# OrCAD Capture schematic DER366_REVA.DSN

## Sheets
1 PAGE2: size A
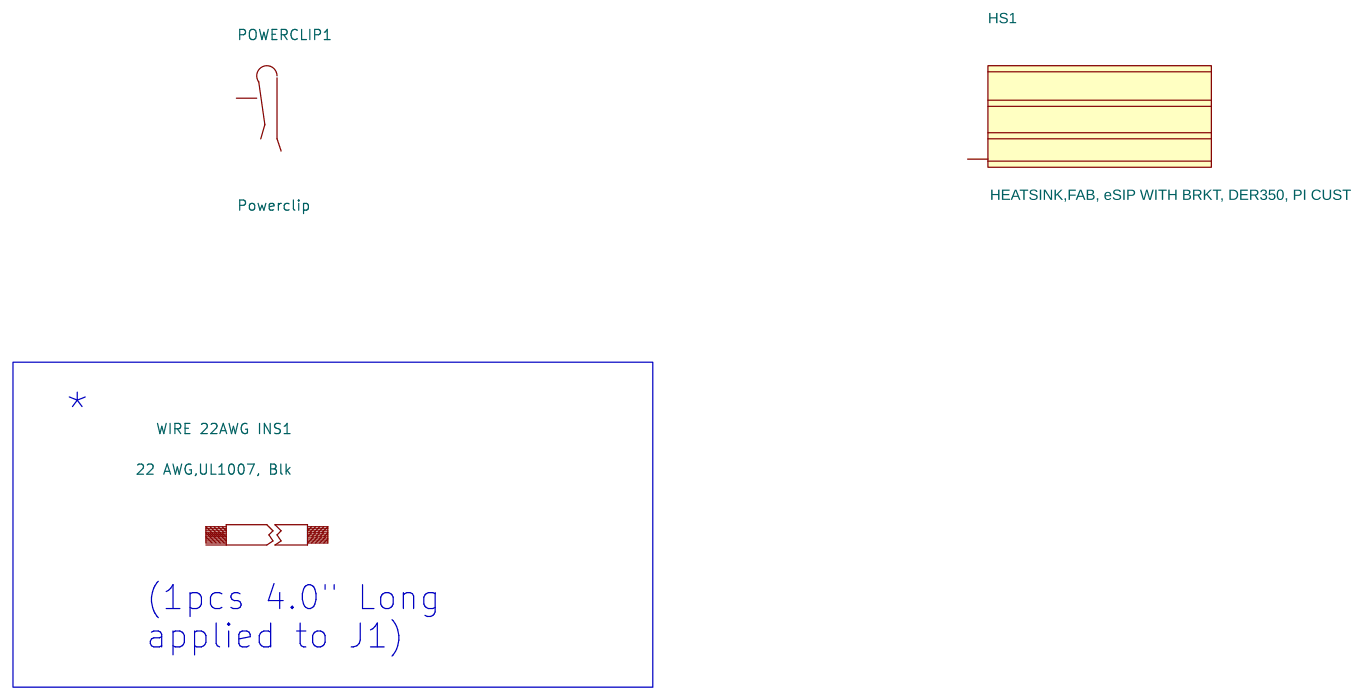
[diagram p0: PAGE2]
2 PAGE1: size C
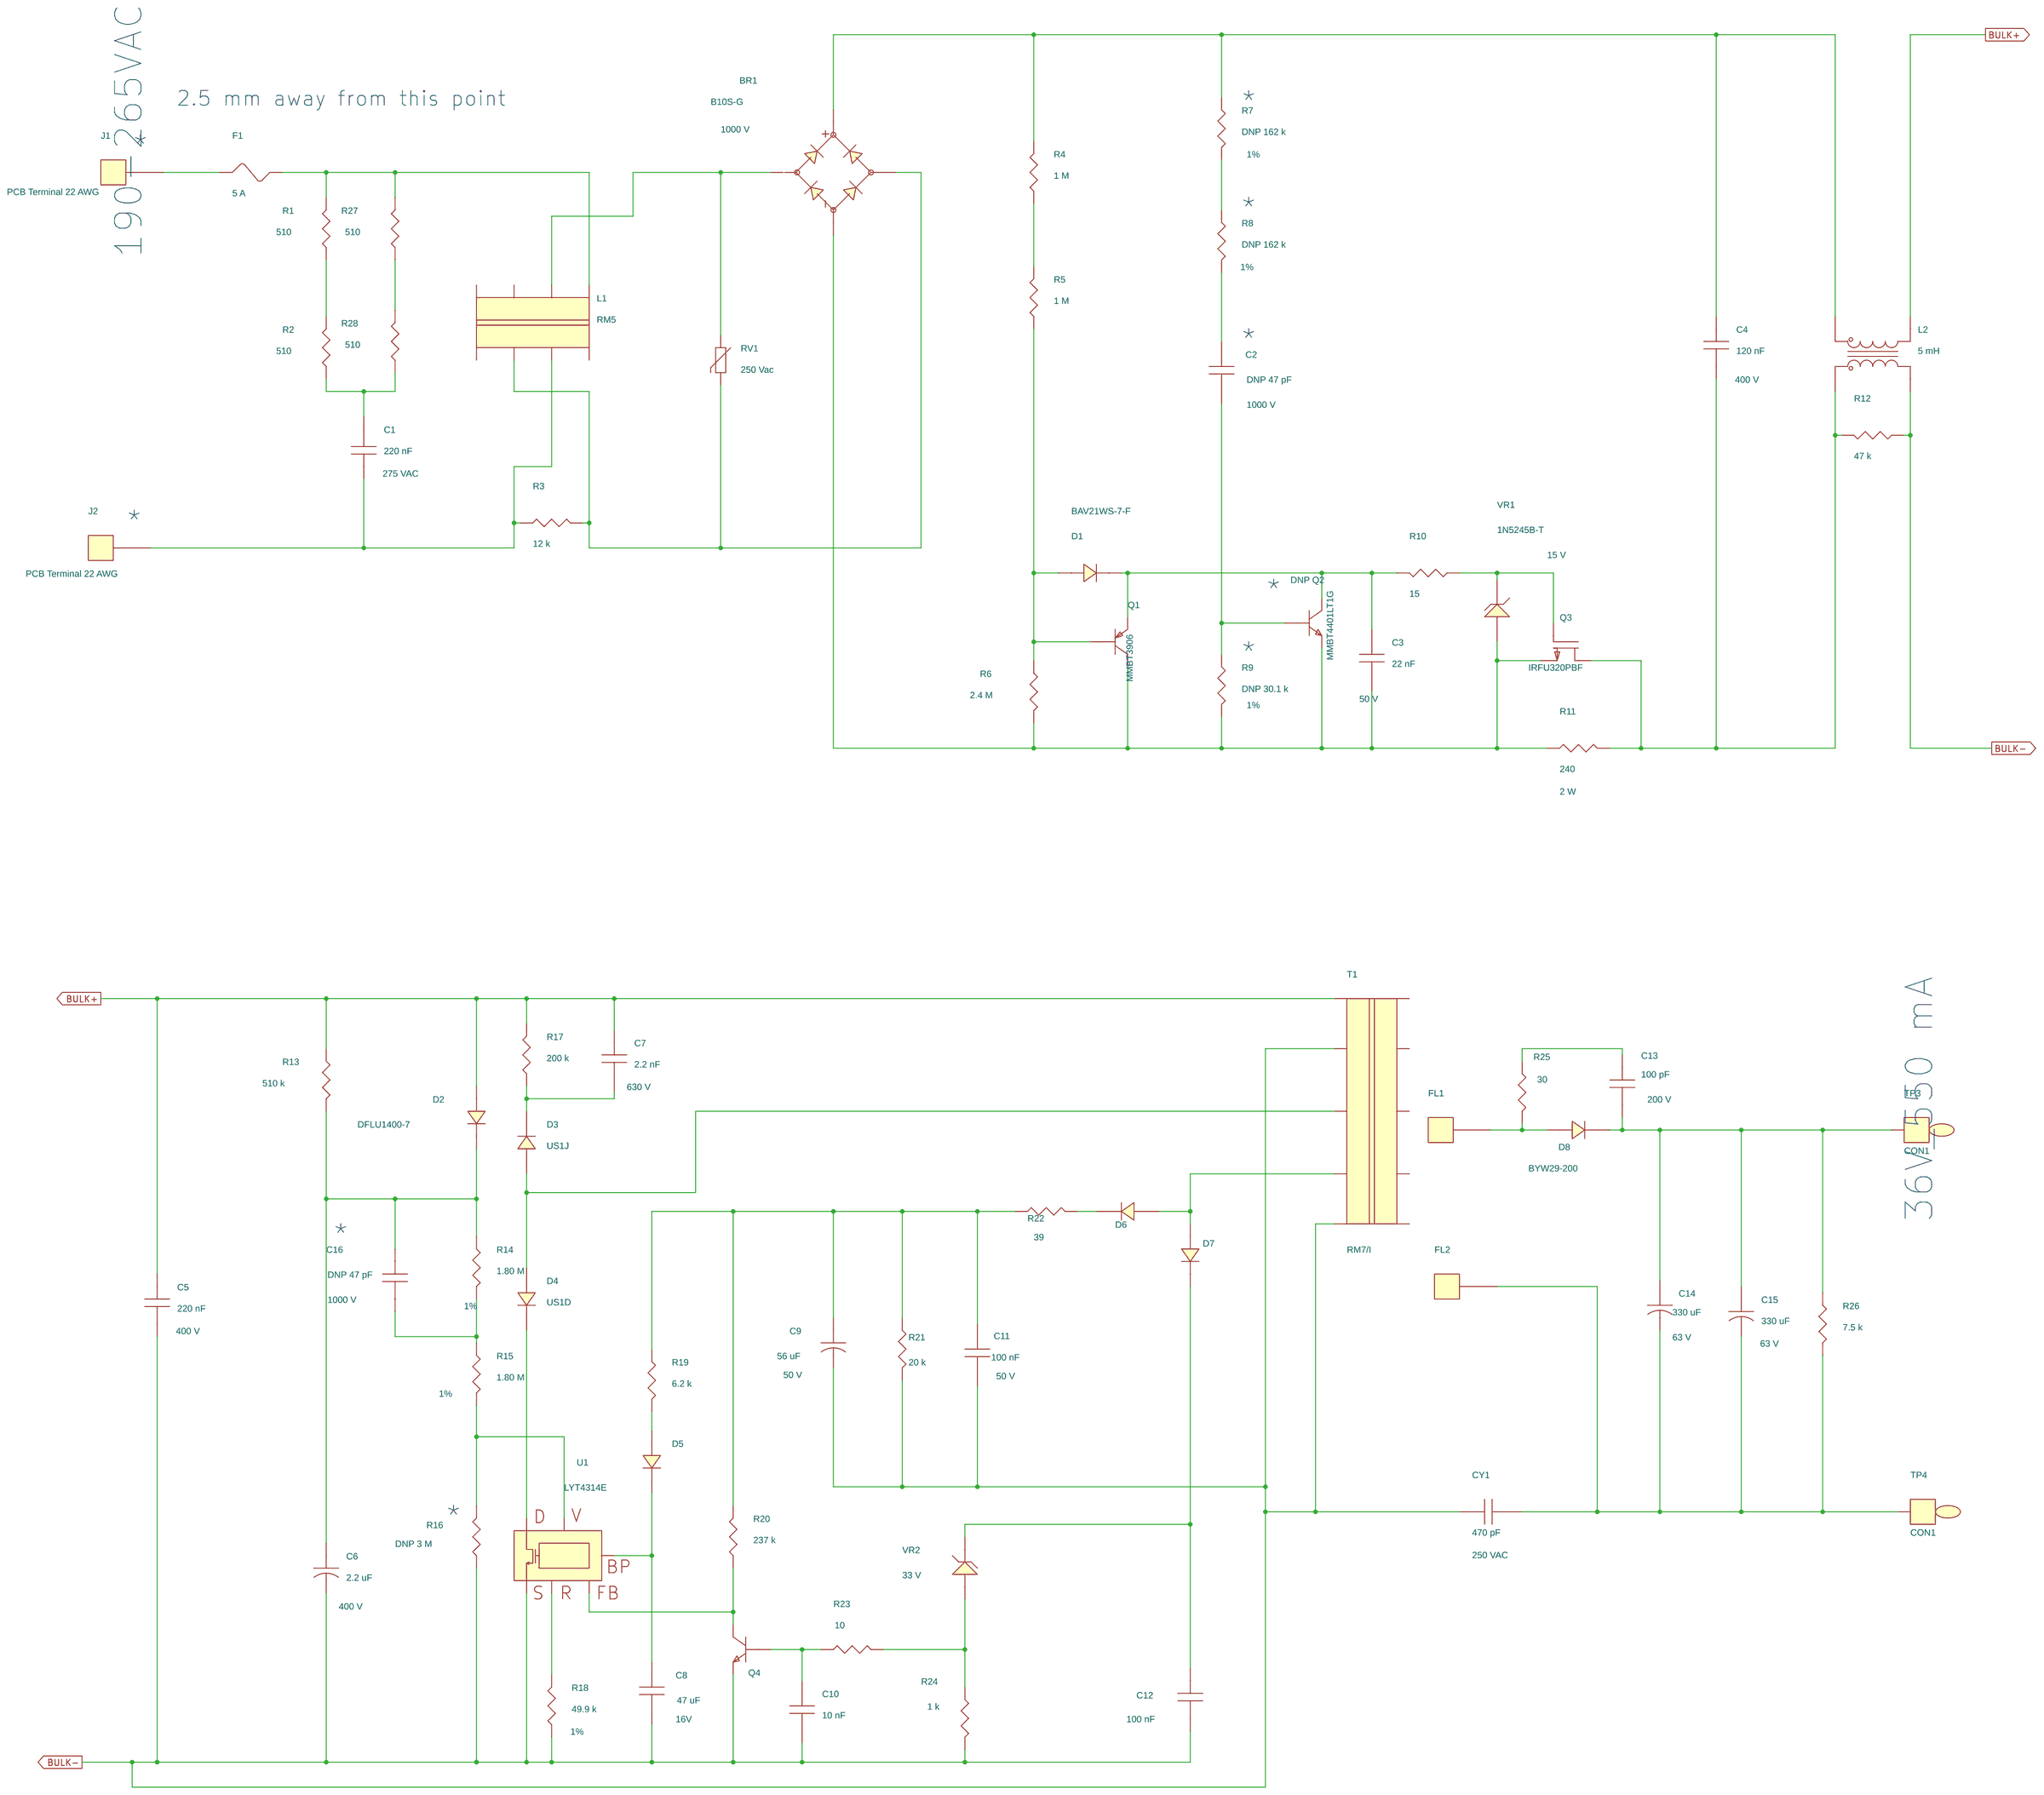
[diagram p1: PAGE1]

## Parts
sheet PAGE1
BR1  B10S-G  [pismsoic4]
C1  220 nF  [pi_np_xcap_rad550x330ls493d040]
C2  DNP 47 pF  [pismc0805]
C3  22 nF  [pismc0603]
C4  120 nF  [pinpcr730x200ls590d40]
C5  220 nF  [pinpcaprad730x230590050]
C6  2.2 uF  [pipolcapcyld250ls100030]
C7  2.2 nF  [pismc1206]
C8  47 uF  [pismc1206]
C9  56 uF  [pipolcapcyld250ls100030]
C10  10 nF  [pismc0603]
C11  100 nF  [pismc0805]
C12  100 nF  [pismc0603]
C13  100 pF  [pismc0805]
C14  330 uF  [pipolcapcyld400ls200040]
C15  330 uF  [pipolcapcyld400ls200040]
C16  DNP 47 pF  [pismc0805]
CY1  470 pF  [pinpcaprad394x275394030]
D1  BAV21WS-7-F  [pismsod323]
D2  DFLU1400-7  [pismddflr120012]
D3  US1J  [pismdsma]
D4  US1D  [pismdsma]
D5  BAV16WS-7-F  [pismsod323]
D6  BAV21WS-7-F  [pismsod323]
D7  BAV21WS-7-F  [pismsod323]
D8  BYW29-200  [pidvt0220acreva]
DNP Q2  MMBT4401LT1G  [pismsot23132]
F1  5 A  [pi_v_axial_160ls150d030]
FL1  PCB Terminal 22 AWG  [pi_hole_22awg]
FL2  PCB Terminal 22 AWG  [pi_hole_22awg]
J1  PCB Terminal 22 AWG  [pi_hole_22awg]
J2  PCB Terminal 22 AWG  [pi_hole_22awg]
L1  RM5  [pi_bobbin_rm5_6p_clp]
L2  5 mH  [piind4p615x420ls350x270040]
Q1  MMBT3906  [pismsot23132]
Q3  IRFU320PBF  [pi_to251aa_123]
Q4  MMBT3904  [pismsot23132]
R1  510  [pismr2512]
R2  510  [pismr2512]
R3  12 k  [pismr0805]
R4  1 M  [pismr1206]
R5  1 M  [pismr1206]
R6  2.4 M  [pismr0805]
R7  DNP 162 k  [pismr1206]
R8  DNP 162 k  [pismr1206]
R9  DNP 30.1 k  [pismr0603]
R10  15  [pismr0603]
R11  240  [pi2wresd200ls725d040]
R12  47 k  [pismr1206]
R13  510 k  [pismr0805]
R14  1.80 M  [pismr1206]
R15  1.80 M  [pismr1206]
R16  DNP 3 M  [pismr0603]
R17  200 k  [pismr1206]
R18  49.9 k  [pismr0603]
R19  6.2 k  [pismr1206]
R20  237 k  [pismr0805]
R21  20 k  [pismr0805]
R22  39  [pismr0805]
R23  10  [pismr0603]
R24  1 k  [pismr0603]
R25  30  [pismr1206]
R26  7.5 k  [pismr1206]
R27  510  [pismr2512]
R28  510  [pismr2512]
RV1  250 Vac  [pidisc350x160ls210x140040]
T1  RM7/I  [pi_bobbin_rm7_8p_clp]
TP3  CON1  [pitpkeystone100x100]
TP4  CON1  [pitpkeystone100x100]
U1  LYT4314E  [piicesip76th]
VR1  1N5245B-T  [pidv200x080x030do35]
VR2  MMSZ5257BS-7-F  [pismsod323]
sheet PAGE2
HS1  HEATSINK,FAB, eSIP WITH BRKT, DER350, PI CUST  [pi_hsk_der350_esip]
POWERCLIP1  Powerclip
WIRE 22AWG INS1  22 AWG,UL1007, Blk

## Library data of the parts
BR1 = DIODE_BRIDGE_~~+-: Disp_Voltage: 1000 V; Part Number: 15-00818-00
C1 = CAP_NP: ALT_SYMBOLS: pinpcaprad550x395490030horz; Disp_Voltage: 275 VAC; FPLIST: pi_np_xcap_rad550x330ls493d040,pinpcaprad550x395490030horz; Part Number: 20-00777-00; Voltage: 275 VAC
C2 C16 = CAP_NP: Disp_Voltage: 1000 V; Part Number: 20-01040-00; Voltage: 1000 V
C3 = CAP_NP: Disp_Voltage: 50 V; Part Number: 20-08617-00; Voltage: 50V
C4 = CAP_NP: Disp_Voltage: 400 V; Part Number: 20-00859-00; Voltage: 400 V
C5 = CAP_NP: Disp_Voltage: 400 V; Part Number: 20-00796-00; Voltage: 400 V
C6 = CAP_POL: ALT_SYMBOLS: pipolcapcyld250ls100030h; Disp_Voltage: 400 V; FPLIST: pipolcapcyld250ls100030,pipolcapcyld250ls100030h; Part Number: 20-01008-00; Voltage: 400 V
C7 = CAP_NP: Disp_Voltage: 630 V; Part Number: 20-08609-00; Voltage: 630 V
C8 = CAP_NP: Disp_Voltage: 16V; Part Number: 20-01116-00; Voltage: 16V
C9 = CAP_POL: ALT_SYMBOLS: pipolcapcyld250ls100030h; Disp_Voltage: 50 V; Part Number: 20-00057-00; Voltage: 50 V
C10 = CAP_NP: Disp_Voltage: 50 V; Part Number: 20-01051-00; Voltage: 50V
C11 = CAP_NP: Disp_Voltage: 50 V; Part Number: 20-00904-00; Voltage: 50 V
C12 = CAP_NP: Disp_Voltage: 50 V; Part Number: 20-00936-00; Voltage: 50 V
C13 = CAP_NP: Disp_Voltage: 200 V; Part Number: 20-00760-00; Voltage: 200 V
C14 C15 = CAP_POL: ALT_SYMBOLS: pipolcapcyld400ls200040800h; Disp_Voltage: 63 V; Part Number: 20-01117-00; Voltage: 63 V
CY1 = CAP_NP: Disp_Voltage: 250 VAC; Part Number: 20-00744-00; Voltage: 250 VAC
D1 D6 D7 = DIODE: Part Number: 15-00385-00
D2 = DIODE: Part Number: 15-00910-00
D3 = DIODE: Part Number: 15-00494-00
D4 = DIODE: Part Number: 15-00492-00
D5 = DIODE: Part Number: 15-00850-00
D8 = DIODE: Part Number: 15-00675-00
DNP Q2 = NPN_BEC: Part Number: 55-00059-00
F1 = FUSE: FPLIST: pi_v_axial_160ls150d030,pi_v_axial_160ls250d030; Part Number: 40-00026-00
FL1 FL2 J1 J2 = TERM_1Pin: Part Number: 35-00008-00
L1 = BRM6_6P_CLP: Part Number: 25-01013-00
L2 = INDUCTOR_4P_revB: Part Number: 30-00352-00
Q1 = PNP_BEC: Part Number: 55-00049-00
Q3 = FET_N_GDS: FPLIST: pito251aa123vf1,pi_to251aa_123; Part Number: 50-00121-00
Q4 = NPN_BEC: Part Number: 55-00048-00
R1 R2 R27 R28 = R: Part Number: 05-05403-00
R3 = R: Part Number: 05-01545-00
R4 R5 = R: Part Number: 05-01424-00
R6 = R: Part Number: 05-01599-00
R7 R8 = R: Disp_Tol: 1%; Part Number: 05-00405-00
R9 = R: Disp_Tol: 1%; Part Number: 05-03230-00
R10 = R: Part Number: 05-01644-00
R11 = R: ALT_SYMBOLS: pi2wresd200ls900d040,pi2wvresd200ls300d040,pi2wvresd200ls400d040; Disp_Power: 2 W; FPLIST: pi2wresd200ls725d040,pi2wresd200ls900d040,pi2wvresd200ls300d040,pi2wvresd200ls400d040; Part Number: 05-02989-00
R12 = R: Part Number: 05-01392-00
R13 = R: Part Number: 05-01584-00
R14 R15 = R: Disp_Tol: 1%; Part Number: 05-03155-00
R16 = R: Part Number: 05-032291-00
R17 = R: Part Number: 05-01407-00
R18 = R: Disp_Tol: 1%; Part Number: 05-03251-00
R19 = R: Part Number: 05-01371-00
R20 = R: Disp_Tol: 1%; Part Number: 05-00816-00
R21 = R: Part Number: 05-01550-00
R22 = R: Part Number: 05-01485-00
R23 = R: Part Number: 05-01640-00
R24 = R: Part Number: 05-01688-00
R25 = R: Part Number: 05-01315-00
R26 = R: Part Number: 05-01373-00
RV1 = VARISTOR: Part Number: 85-00032-00
T1 = BRM7_8P_CLP: Part Number: 25-01014-00
TP3 = TESTPOINT: Part Number: 35-00080-00
TP4 = TESTPOINT: Part Number: 35-00079-00
U1 = LNK40X_eSIP: Part Number: 10-00641-00
VR1 = DIODE_ZENER: ALT_SYMBOLS: pidax375x070030do35; Disp_Voltage: 15 V; FPLIST: pidv200x080x030do35,pidax375x070030do35; Part Number: 15-00752-00
VR2 = DIODE_ZENER: Disp_Voltage: 33 V; Part Number: 15-00992-00
HS1 = HS-PI_CUSTOM1: Part Number: 61-00095-01
POWERCLIP1 = Powerclip: Part Number: 60-00028-00
WIRE 22AWG INS1 = Wire_22AWG_Ins: Part Number: 66-00053-00

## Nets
BULK+: C5.1 C7.1 D2.2 L2.4 R13.1 R17.2 T1.1
BULK-: C5.2 C6.2 C8.2 C9.2 C10.2 C11.2 C12.2 CY1.1 L2.2 Q4.2(EMITTER) R12.1 R16.2 R18.2 R21.2 R24.2 T1.8 T1.CLP1 U1.5(S)
N2034910: C14.2 C15.2 CY1.2 FL2.1 R26.2 TP4.1
N2960943: C4.2 L2.1 Q3.2(D) R11.2 R12.2
N2960957: Q3.1(G) R10.1 VR1.1
N3477441: C9.1 C11.1 R19.2 R20.2 R21.1 R22.2
N3478377: C8.1 D5.1 U1.4(BP)
N3479119: C13.2 C14.1 C15.1 D8.1 R26.1 TP3.1
N3481544: C6.1 C16.1 D2.1 R13.2 R14.1
N3482634: R15.2 R16.1 U1.2(V)
N3538375: BR1.3 C4.1 L2.3 R4.2 R7.1
N3564395: BR1.4 C3.2 DNP Q2.2(EMITTER) Q1.3(COLLECTOR) Q3.3(S) R6.2 R9.2 R11.1 VR1.2
N3568268: C1.1 J2.1 L1.4 R3.1
N3576797: BR1.2 L1.2 RV1.1
N3617192: D4.1 U1.7(D)
N3617220: D3.2 D4.2 T1.7
N3617246: C7.2 D3.1 R17.1
N3624850: R18.1 U1.1(R)
N3624949: Q4.3(COLLECTOR) R20.1 U1.3(FB)
N3631334: D8.2 FL1.1 R25.2
N3631358: C13.1 R25.1
N3634006: C10.1 Q4.1(BASE) R23.1
N3634524: R23.2 R24.1 VR2.2
N3634757: C12.1 D7.1 VR2.1
N3672532: BR1.1 L1.3 R3.2 RV1.2
N3672950: F1.1 L1.1 R1.2 R27.2
N3675846: C3.1 D1.1 DNP Q2.3(COLLECTOR) Q1.2(EMITTER) R10.2
N3676738: D1.2 Q1.1(BASE) R5.1 R6.1
N3678831: D5.2 R19.1
N3689416: F1.2 J1.1
N3689420: R1.1 R2.2
N3689424: C1.2 R2.1 R28.1
N3690239: R4.1 R5.2
N3694128: R7.2 R8.1
N3694132: C2.1 R8.2
N3694136: C2.2 DNP Q2.1(BASE) R9.1
N3695980: C16.2 R14.2 R15.1
N3696337: D6.2 D7.2 T1.6
N3706359: D6.1 R22.1
N3724230: R27.1 R28.2

Not connected (* = marked no-connect by the designer): HS1 1; L1 5 6 CLP1 CLP2; T1 2 3 4 5 CLP2

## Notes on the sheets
sheet 1
- *
- (1pcs 4.0" Long
  applied to J1)
sheet 2
- 2.5 mm away from this point
- *
- *
- *
- 190-265VAC
- *
- *
- *
- *
- *
- 36V_550 mA
- *
